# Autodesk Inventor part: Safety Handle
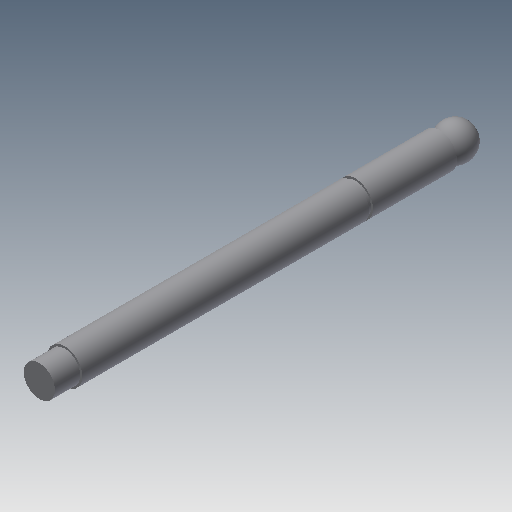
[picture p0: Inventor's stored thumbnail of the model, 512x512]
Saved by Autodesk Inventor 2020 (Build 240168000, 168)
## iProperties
Created: 2002-02
Part Number: Safety Handle
Document SubType Name: Modeling
Designer: ***
Density: 1 g/cm^3
Material: Generic
Mass: 54.3914 g
Surface Area: 130.219 cm^2
Volume: 54.3914 cm^3
Appearance: Default
Control State: 0
Master: False
Checked Out: False
Shininess: 77.0
Length Units: 11269
Angle Units: 11279
Time Units: 11290
Mass Units: 11283
Length Display Precision: 3
Angle Display Precision: 2
Density: 0.0
Volumn: 0.0
Area: 0.0
PropertySet Name: Model Information
Author: ***
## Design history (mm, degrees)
sketch "Sketch1"
  geometry: L1 (0, 205)-(8, 205); L2 (8, 205)-(8, 192); L3 (8, 192)-(9, 192); L4 (9, 192)-(9, 45); L5 (9, 45)-(8, 45); L6 (8, 45)-(8, 43); L7 (8, 43)-(9, 43); L8 (9, 43)-(9, 0); L9 (9, 0)-(0, 0); L10 (0, 0)-(0, 205)
  constraints: 20 end point, 7 parallel, 1 collinear, 1 horizontal, 1 perpendicular
  dimensions: "d0" = 13 distance of L1.end L2.end; "d1" = 2 distance of L4.end L7.end; "d2" = 43 distance of L7.end L8.end; "d3" = 205 distance of L9.end L1.start; "d4" = 16 diameter of L2 L10; "d5" = 18 diameter of L4 L10; "d6" = 16 diameter of L6.end L10
revolve "Revolution1" sketch "Sketch1" stored, may be unused: angle "d7" = 90 deg
sketch "Sketch2"
  geometry: L1 (0, 1)-(0, -17); L2 (-9, 0)-(9, 0) reference; A1 r 9 centre (0, -8) between (0, -17) and (0, 1)
  constraints: 2 end point, 2 point on circle, 1 centre point, 1 midpoint, 1 vertical
  dimensions: "d8" = 9 radius of A1; "d9" = 1 distance from line of L2 L1.start
revolve "Revolution2" sketch "Sketch2" stored, may be unused: angle "d10" = 90 deg
body "Solid1"
